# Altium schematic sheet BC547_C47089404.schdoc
size 127 x 101 mm
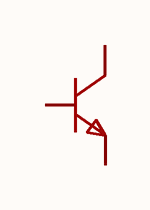
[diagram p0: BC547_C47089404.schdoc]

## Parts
Q?  bc547  [TO-92-3_L4.9-W3.7-P1.27-L]  (value not drawn)

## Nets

Not connected (* = marked no-connect by the designer): Q? 1(C) 2(B) 3(E)

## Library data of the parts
Q? = bc547: 晶体管类型:NPN;集电极电流(Ic):100mA;集射极击穿电压(Vceo):45V;耗散功率(Pd):625mW;直流电流增益(hFE):800;; Manufacturer: CJ(江苏长电/长晶); Symbol: BC547_C47089404; AddInBom: yes; ModelId: aafe8e06f2154e7c93506efd0d6632dd; ModelTransform: 176.28752,144.88554,0,180,0,0,0,20.669,-196.85; type: NPN; Current - Collector(Ic): 100mA; Collector - Emitter Voltage VCEO: 45V; Pd - Power Dissipation: 625mW; DC Current Gain: 800; Transition frequency(fT): 150MHz; Current - Collector Cutoff: 100nA; Vce Saturation(VCE(sat)): 300mV; Emitter-Base Voltage(Vebo): 6V; Number: 1个NPN; Configuration: 独立式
